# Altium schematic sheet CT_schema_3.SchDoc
size 258 x 142 mm
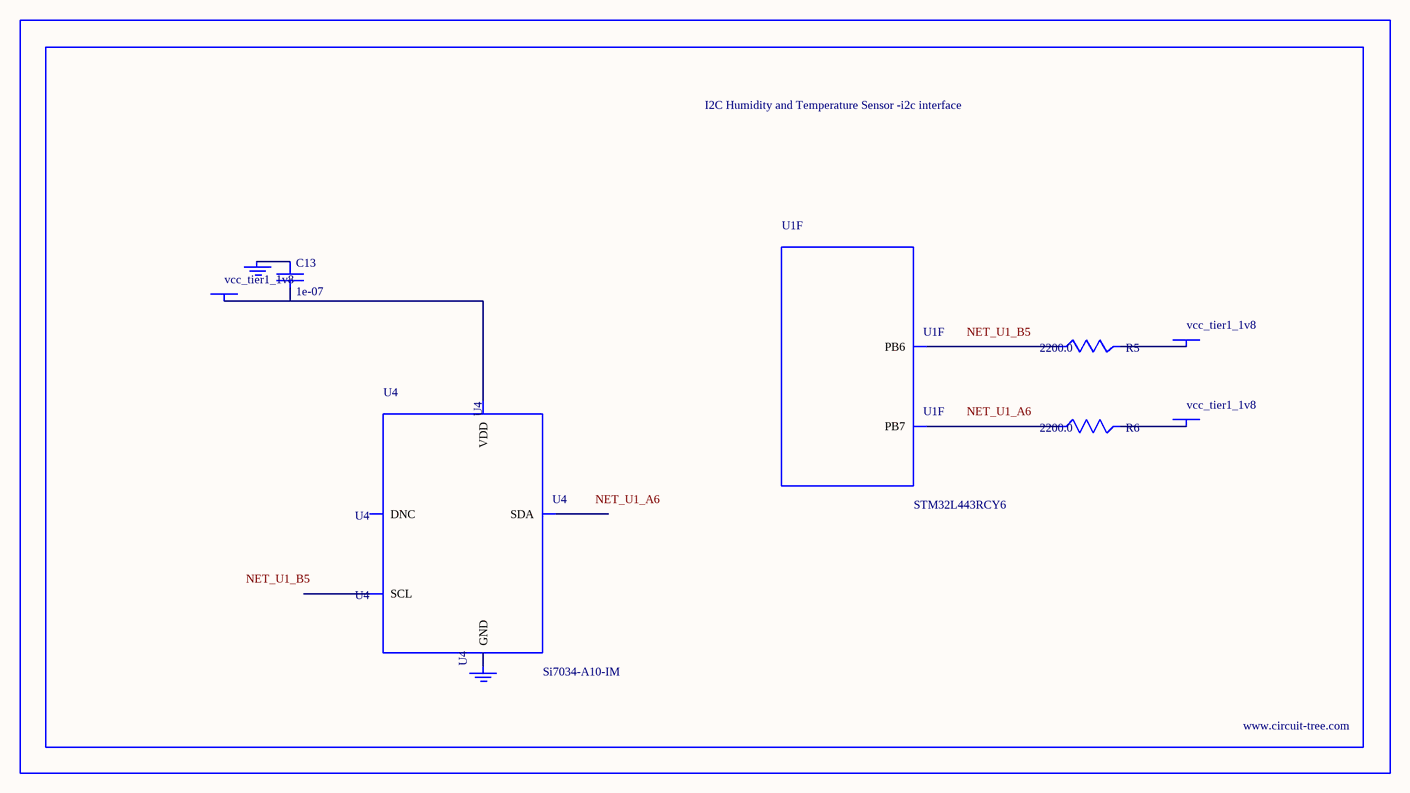
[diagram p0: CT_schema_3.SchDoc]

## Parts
BORDER2  (no value)
C13  1e-07  [C0402]
GND_INSTANCE_2_0  (no value)
GND_INSTANCE_2_1  (no value)
POWER_INSTANCE_2_0  vcc_tier1_1v8
POWER_INSTANCE_2_1  vcc_tier1_1v8
POWER_INSTANCE_2_2  vcc_tier1_1v8
R5  2200.0  [R0603]
R6  2200.0  [R0603]
U1  STM32L443RCY6  [WLCSP64]  (part F of 7)
U4  Si7034-A10-IM  [SI7034-A10-IM]

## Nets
NetC13_1: C13.1 GND_INSTANCE_2_0.0(GND)
NetC13_2: C13.2 POWER_INSTANCE_2_0.0(PWR) U4.1(VDD)
NetGND_INSTANCE_2_1_0: GND_INSTANCE_2_1.0(GND) U4.5(GND)
NetPOWER_INSTANCE_2_1_0: POWER_INSTANCE_2_1.0(PWR) R5.2
NetPOWER_INSTANCE_2_2_0: POWER_INSTANCE_2_2.0(PWR) R6.2
NetR5_1: R5.1 U1.B5(PB6)
NetR6_1: R6.1 U1.A6(PB7)

Not connected (* = marked no-connect by the designer): U4 2(SCL) 3(DNC) 4(SDA)

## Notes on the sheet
- Labels drawn without touching a wire or pin: NET_U1_A6, NET_U1_B5

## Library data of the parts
BORDER2 = BORDER_PAGE2
C13 = C0402C104K3RACTU
GND_INSTANCE_2_0 GND_INSTANCE_2_1 = GND
POWER_INSTANCE_2_0-POWER_INSTANCE_2_2 = PWR
R5 R6 = RC0603JR-072K2L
